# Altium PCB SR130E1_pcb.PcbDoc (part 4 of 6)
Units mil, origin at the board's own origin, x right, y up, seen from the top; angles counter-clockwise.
Board outline 5700 x 4800 mil, 6 copper layers (Top Layer, Signal Layer 1, Signal Layer 2, Signal Layer 3, Signal Layer 4, Bottom Layer), stack 61.4 mil thick; 452 components, 288 nets, 1391 pads, 911 vias.
Unrouted connection lines stored in the file: 523.
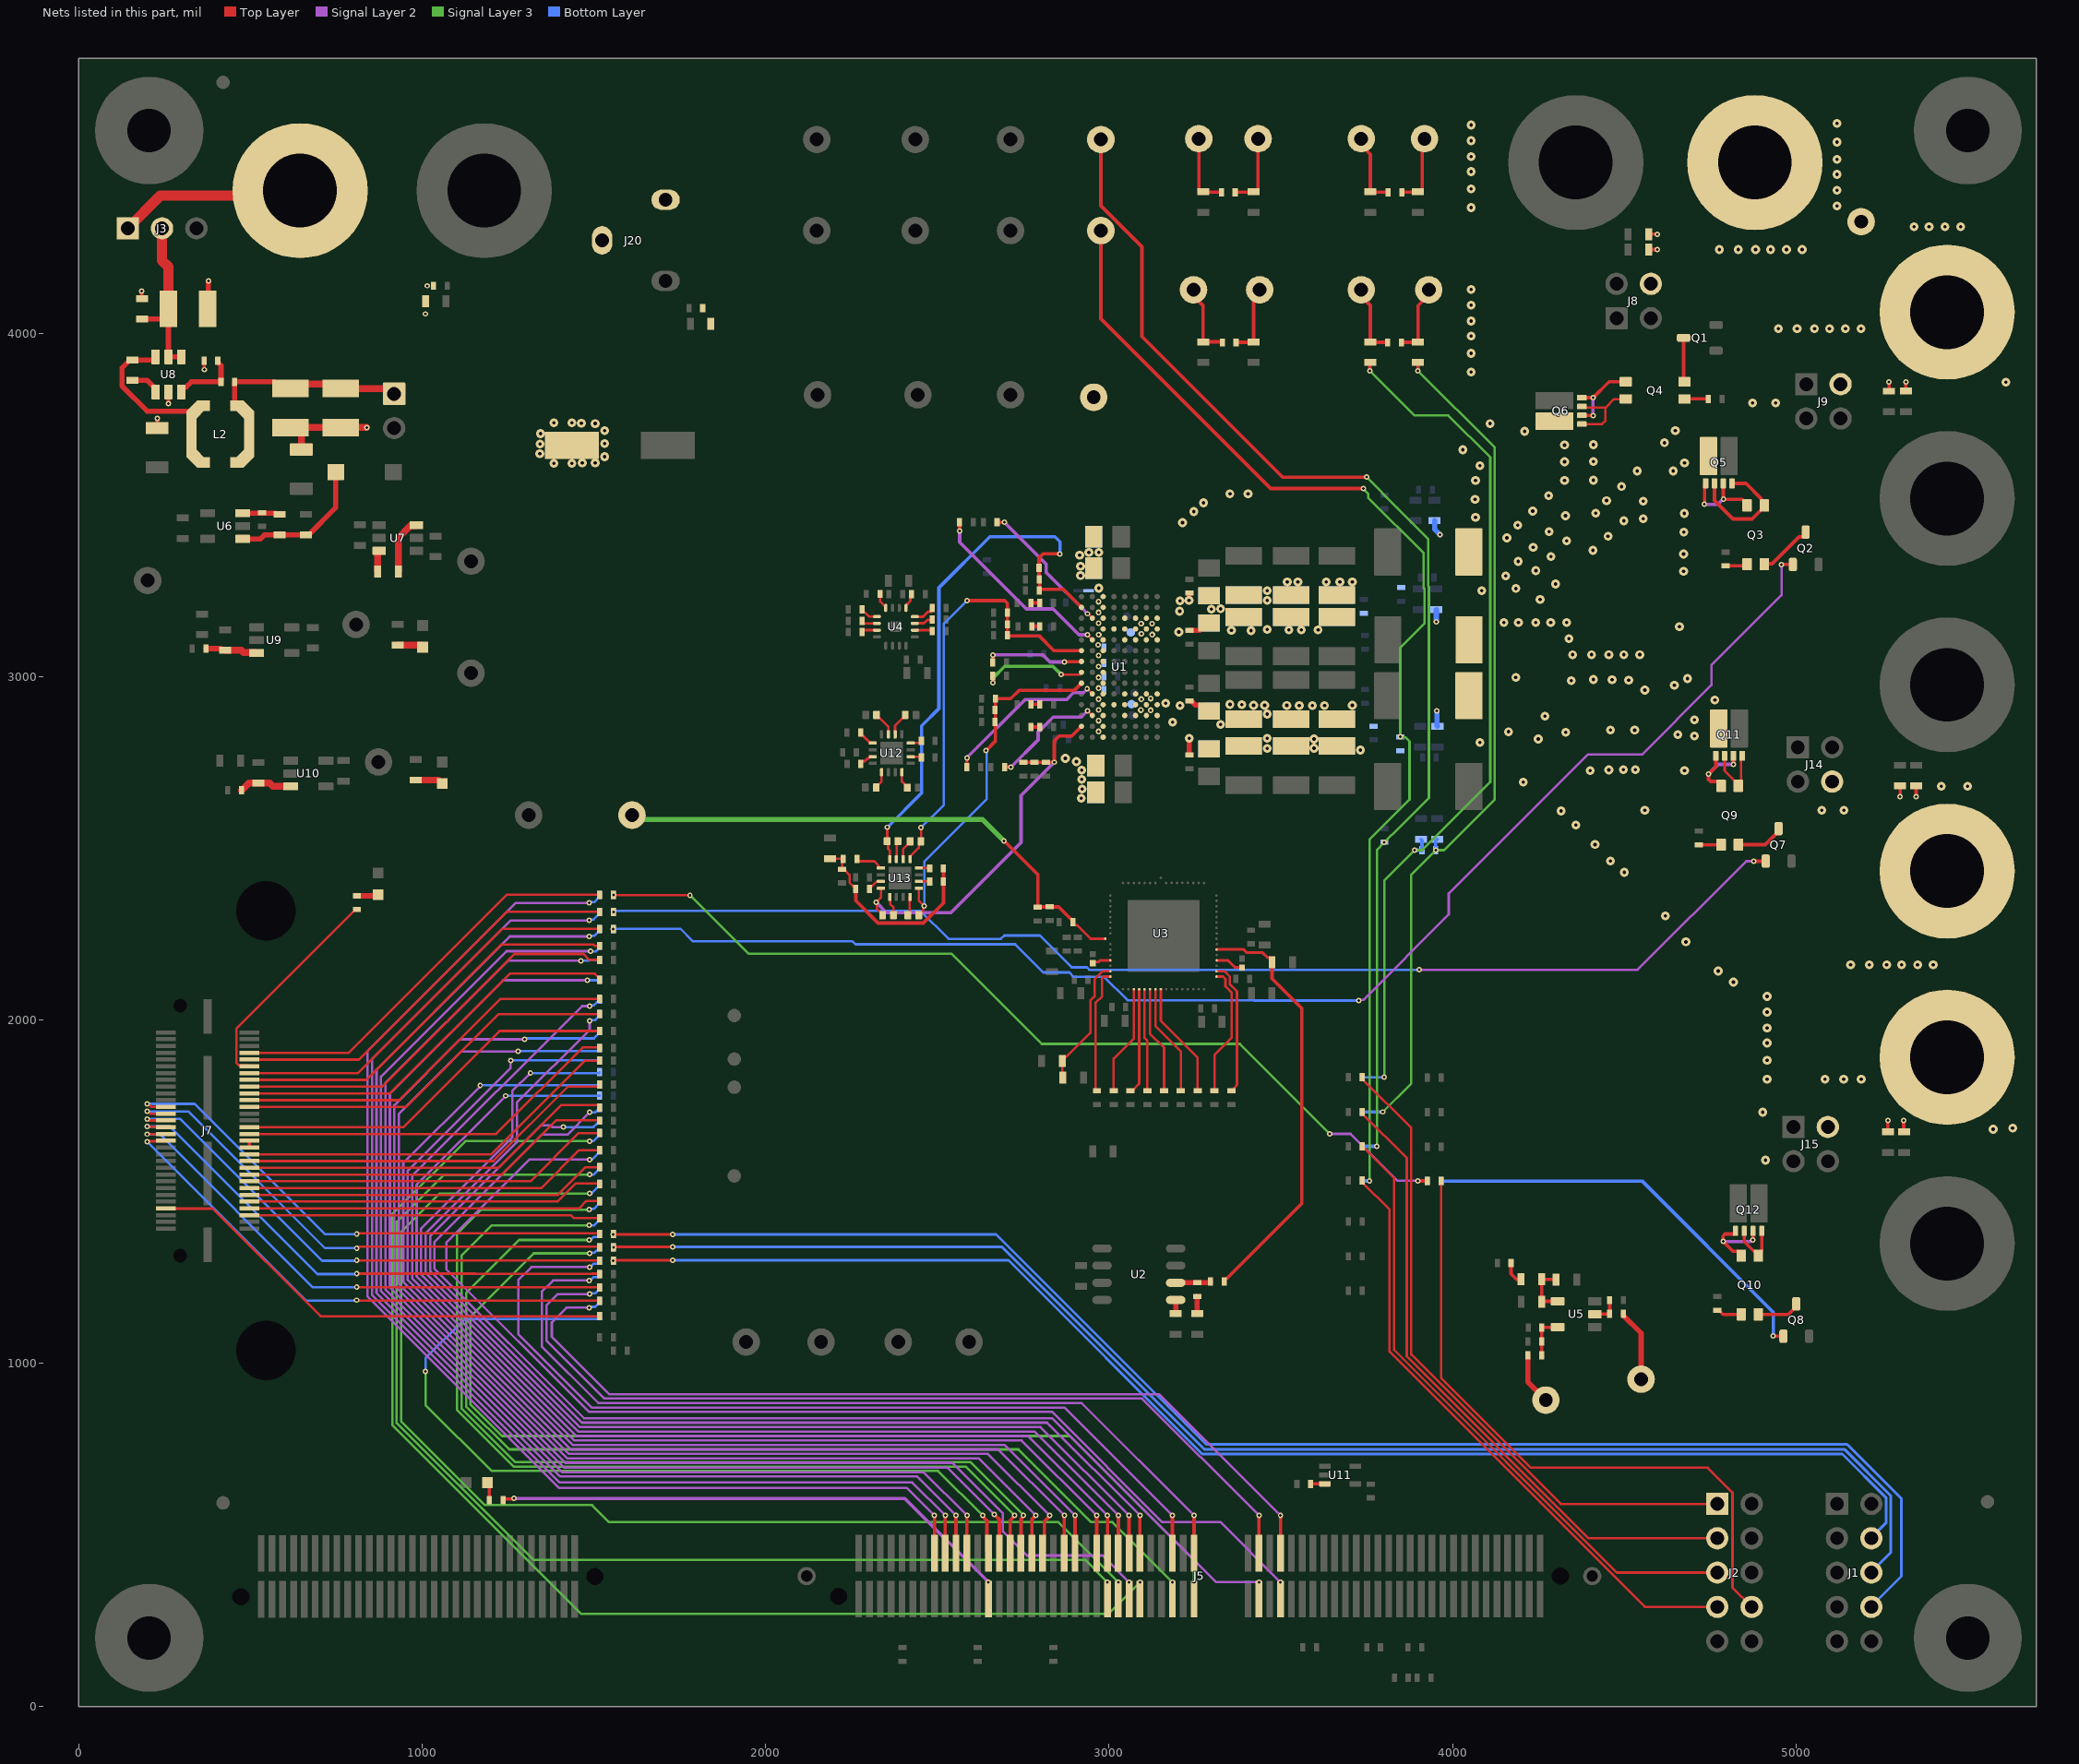
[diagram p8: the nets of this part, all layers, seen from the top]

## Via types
v1: diameter 26, hole 10, Top Layer to Bottom Layer, tented both sides, 435 vias
v2: diameter 16, hole 8, Top Layer to Bottom Layer, tented both sides, 208 vias
v3: diameter 16, hole 8, Top Layer to Bottom Layer, 145 vias
v4: diameter 16, hole 8, Top Layer to Bottom Layer, tented bottom, 46 vias
v5: diameter 19.68, hole 8, Top Layer to Bottom Layer, tented both sides, 35 vias
v6: diameter 17, hole 8, Top Layer to Bottom Layer, 30 vias
v7: diameter 18, hole 8, Top Layer to Bottom Layer, tented both sides, 6 vias
v8: diameter 16, hole 8, Top Layer to Bottom Layer, tented top, 4 vias
v9: diameter 19.68, hole 8, Top Layer to Bottom Layer, 1 vias
v10: diameter 17, hole 8, Top Layer to Bottom Layer, tented both sides, 1 vias

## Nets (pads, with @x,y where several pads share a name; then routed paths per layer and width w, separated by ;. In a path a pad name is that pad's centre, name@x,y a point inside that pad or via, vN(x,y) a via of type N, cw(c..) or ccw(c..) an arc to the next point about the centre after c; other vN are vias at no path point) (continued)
EN_RLY2: Q2.1 R134.1 R166.1 | length 4168.7
  Top Layer w10: v4(4958.09,3326.01) Q2.1@4991.18,3326.01
  Signal Layer 2 w7: v4(3727.26,2056.06) 3729.18,2057.97 3740.14,2057.97 3989.14,2306.97 3989.14,2368.14 4393.77,2772.78 4551.73,2772.78 4754.05,2975.09 4754.05,3032.49 4958.09,3236.53 v4(4958.09,3326.01)
  Bottom Layer w7: R134.1@1557.16,2264.65 1557.64,2265.13 1751.77,2265.13 1787.66,2229.24 2252.6,2229.24 2261.8,2220.04 2726.74,2220.04 2808.73,2138.06 2884.4,2138.06 2897.4,2125.06 2985.84,2125.06 3053.74,2057.15 3421.8,2057.15 3422.9,2056.06 v4(3727.26,2056.06)
  other v3: 1556.67,2264.16
EN_RLY3: Q7.1 R135.1 R167.1 | length 3570.1
  Top Layer w7: R167.1@1557.16,2314.38 R167.1@1559.67,2316.9 ; Q7.1@4911.79,2461.82 Q7.1@4912.23,2462.26
  Top Layer w10: v4(4877.1,2461.82) Q7.1@4911.79,2461.82
  Signal Layer 2 w7: v4(3903.67,2145.63) 3903.81,2145.49 4538.98,2145.49 4855.31,2461.82 v4(4877.1,2461.82)
  Bottom Layer w7: R135.1@1557.16,2314.72 1559.34,2316.9 1810,2316.9 2451.4,2316.9 2532.75,2235.55 2685.3,2235.55 2695.31,2245.56 2798.38,2245.56 2891.03,2152.91 2935.42,2152.91 2942.77,2145.56 3903.6,2145.56 v4(3903.67,2145.63)
  other v3: 1557.44,2314.67
EN_RLY4: Q8.1 R68.1 | length 1224.3
  Top Layer w10: v3(4934.22,1079.67) 4934.89,1079.01 4962.91,1079.01 Q8.1@4963.57,1078.35
  Bottom Layer w10: R68.1@3966.8,1530.55 4552.02,1530.55 4934.22,1148.34 v3(4934.22,1079.67)
EN_RLY4_H: R68.2 R69.2 R136.1 R168.1 | length 2744.3
  Top Layer w7: v3(1557.16,2363.94) 1558.22,2362.87 v3(1780,2362.87)
  Top Layer w10: v2(3899.32,1531.1) 3899.6,1530.83 3926.53,1530.83 R69.2@3926.8,1530.55
  Signal Layer 2 w7: v4(3642.98,1668) 3703.25,1668 3840.14,1531.1 v2(3899.32,1531.1)
  Signal Layer 3 w7: v3(1780,2362.87) 1950.36,2192.51 2541,2192.51 2803.78,1929.73 3381.25,1929.73 v4(3642.98,1668)
  Bottom Layer w7: R136.1@1557.16,2363.65 R136.1@1558.41,2364.91
  Bottom Layer w10: v2(3899.32,1531.1) 3899.6,1530.83 3926.53,1530.83 R68.2@3926.8,1530.55
EN_RLY4_header: J2.8 R69.1 | length 1916.6
  Top Layer w7: R69.1@3966.8,1530.55 3966.8,956.93 4228.33,695.4 4743.31,695.4 4815.51,623.2 4815.51,345.95 J2.8@4871.22,290.24
EPWM_EX_1: J1.4 R119.1 R174.2 | length 4125.6
  Top Layer w8: R174.2@1557.16,1298.37 1558.3,1299.52 v3(1730,1299.52)
  Bottom Layer w8: v3(1730,1299.52) 2707.29,1299.52 3271.4,735.4 5135.17,735.4 5262.15,608.42 5262.15,534.61 J1.4@5219.67,492.13
  other v3: 1556.76,1297.97
EPWM_EX_2: J1.6 R140.2 R175.2 | length 4264.7
  Top Layer w8: R175.2@1557.16,1337.17 1558.13,1338.15 v3(1730,1338.15)
  Bottom Layer w8: v3(1730,1338.15) 2688.46,1338.15 3277.2,749.4 5140.97,749.4 5276.15,614.22 5276.15,448.61 J1.6@5219.67,392.13
  other v3: 1557.43,1337.17
EPWM_EX_3: J1.8 R141.2 R176.2 | length 4419
  Top Layer w8: R176.2@1557.16,1375.98 1558.1,1375.03 v3(1730,1375.03)
  Bottom Layer w8: v3(1730,1375.03) 2671.38,1375.03 3282.5,763.91 5149.16,763.91 5307.15,605.91 5307.15,379.61 J1.8@5219.67,292.13
  other v3: 1556.18,1375.01
FB1: D9.1 R26.1 R27.2 R28.1 U1.A13 U13.16 | length 1619.9
  Top Layer w7: v2(2354.77,2560.63) 2354.36,2560.23 2354.36,2520.66 D9.1@2353.96,2520.25 2356.97,2517.24 2356.97,2497.94 2361.38,2493.53 U13.16@2361.38,2467.89
  Top Layer w10: v2(2857.31,3356.88) 2807.59,3356.88 2796.23,3345.53 R26.1@2796.23,3316.25 2796.42,3316.06 2796.42,3284.63 2797.93,3283.12 2797.93,3250.67 2797.87,3250.61 2797.87,3253.74 2867.2,3253.74 U1.A13@2919.84,3201.1
  Bottom Layer w10: v2(2354.77,2560.63) 2454.63,2660.5 2454.63,2856.24 2504.64,2906.25 2504.64,3258.28 2653.37,3407 2842.44,3407 2857.31,3392.14 v2(2857.31,3356.88)
FB2: D12.1 R29.1 R30.2 R34.1 U1.A9 U13.13 | length 1271.2
  Top Layer w7: U13.13@2420.44,2467.89 2421.66,2469.12 2421.66,2476.21 2446.23,2500.78 2446.23,2513.65 D12.1@2452.58,2520 ; D12.1@2452.54,2520.03 v2@2452.54,2559.34
  Top Layer w10: v2(2586.16,3221) 2696.17,3221 2704.19,3212.98 2704.19,3183.67 2704.31,3183.55 R34.1@2704.31,3151.74 2704.31,3118.44 2796.19,3118.44 2839.52,3075.12 U1.A9@2919.84,3075.12
  Bottom Layer w7: v2(2452.51,2559.37) 2519.34,2626.19 2519.34,3154.18 v2(2586.16,3221)
FB3: D11.1 R38.2 R39.1 R52.1 U1.A6 U13.9 | length 1053.4
  Top Layer w7: D11.1@2445.95,2304.57 2445.95,2306.54 2460.18,2320.77 2460.18,2329.43 v2(2461.9,2331.15) 2445.99,2347.06 2445.99,2382.02 2446.03,2382.06 U13.9@2446.03,2383.25
  Top Layer w10: v2(2641.82,2783.86) 2668.97,2811.01 2668.97,2870.49 2668.97,2902.01 R38.2@2668.97,2935.46 2713.82,2935.46 2737.62,2959.26 2898.47,2959.26 U1.A6@2919.84,2980.63
  Bottom Layer w7: v2(2461.9,2331.15) 2461.9,2461.03 2644.03,2643.16 2644.03,2779.21 2641.82,2781.42 v2(2641.82,2783.86)
FB4: D10.1 R32.1 R33.2 R36.1 U1.A2 U13.4 | length 1134.5
  Top Layer w7: U13.4@2335.79,2383.25 2335.79,2356.24 v2(2322.03,2342.48) 2323.55,2340.96 2323.55,2323.98 2340.99,2306.54 D10.1@2340.99,2304.57
  Top Layer w10: R36.1@2750.26,2750.14 R36.1@2750.89,2750.14 R33.2@2783.14,2750.14 R32.1@2815.92,2750.14 2819.04,2750.14 2819.1,2750.08 2840.68,2750.08 v2(2840.74,2750.02) ; v2@2840.62,2750.14 2840.74,2750.26 2840.74,2812.12 2855.43,2826.81 2892,2826.81 U1.A2@2919.84,2854.64
  Signal Layer 2 w10: v2(2322.03,2342.48) 2352.36,2312.15 2539.95,2312.15 2743.77,2515.97 2743.77,2653.04 v2(2840.74,2750.02)
HVSS: C84.2 R85.1 R89.1 TP26.1 U3.25 | length 1591.5
  Top Layer w7: R85.1@2892.57,2285.57 2892.57,2281.23 2897.54,2276.26 2906.41,2276.26 2946.48,2236.18 U3.25@2989.41,2236.18
  Top Layer w10: v4(2693.95,2521.39) 2792.66,2422.68 2792.66,2328.18 2793.16,2328.68 2826.33,2328.68 C84.2@2826.7,2329.06 ; C84.2@2824.61,2331.14 C84.2@2826.7,2329.06 ; R85.1@2892.57,2285.57 2892.57,2290.07 2853.58,2329.06 C84.2@2826.7,2329.06
  Signal Layer 3 w15: TP26.1@1611.19,2596.17 1623.57,2583.79 2631.55,2583.79 v4(2693.95,2521.39)
ISEN4+_header: J2.1 R43.1 | length 1937.9
  Top Layer w7: R43.1@3737.27,1832.72 3737.27,1828.22 3879.91,1685.57 3879.91,1025.44 4315.11,590.24 J2.1@4771.22,590.24
ISEN4+_powerSch: C67.2 R18.2 R42.1 R56.1 | length 2545.3
  Top Layer w7: v2@3759.2,3889.9 v2(3759.45,3889.9)
  Top Layer w10: v2@3759.2,3889.9 3759.45,3890.15 3759.45,3912.84 R18.2@3761.04,3914.42
  Signal Layer 3 w7: v2(3759.45,3889.9) 3889.23,3760.12 3988.46,3760.12 4110,3638.58 4110,2692.37 3911.64,2494.01 3889.66,2494.01 3801.73,2406.07 v2(3801.73,1832.72)
  Bottom Layer w7: R42.1@3737.27,1832.72 v2(3801.73,1832.72)
  Bottom Layer w10: v2(3890.07,2494.01) 3908.73,2494.01 3908.83,2494.11 C67.2@3911.23,2494.11 3911.23,2522.87 R56.1@3908.18,2525.92
ISEN4-_header: J2.3 R45.1 | length 1889.1
  Top Layer w7: R45.1@3737.27,1731.68 3737.27,1727.18 3866.91,1597.54 3866.91,1020.05 4396.73,490.24 J2.3@4771.22,490.24
ISEN4-_powerSch: C67.1 R19.2 R44.1 R59.1 | length 2518.2
  Top Layer w10: v2(3899.6,3889.9) R19.2@3899.6,3914.42
  Signal Layer 3 w7: v2(3797.52,1731.68) 3879.91,1814.07 3879.91,2422.59 v2(3951.33,2494.01) 3975.32,2494.01 4123,2641.68 4123,3666.5 v2(3899.6,3889.9)
  Bottom Layer w10: R44.1@3737.27,1731.68 v2(3797.52,1731.68) ; v2(3951.33,2494.01) C67.1@3951.23,2494.11 3951.23,2521.41 R59.1@3955.74,2525.92
LED_BLINK_C2K: J5.96 R148.2 | length 1565.7
  Top Layer w10: R148.2@1235.69,601.61 1235.69,601.71 1238.19,604.21 1265.55,604.21 v3(1267.46,606.12) ; J5.96@2649.09,313.07 v3(2649.09,362.57)
  Signal Layer 2 w10: v3(1267.46,606.12) 2405.54,606.12 v3(2649.09,362.57)
LED_BLINK_PHI: J7.50 R169.2 | length 636.8
  Top Layer w7: J7.50@497,1864.56 494.5,1867.06 466.27,1867.06 459,1874.33 459,1974.59 805.5,2321.09 R169.2@810,2321.09
LENS4-_powerSch: R48.1 R73.2 TP21.1 | length 3435.5
  Top Layer w10: TP21.1@2976.27,4298.34 2976.27,4041.56 3470.74,3547.08 v2(3741.19,3547.08)
  Signal Layer 3 w7: v2(3741.19,3547.08) 3741.19,3545.46 3754.62,3532.02 3754.62,3520.92 3916.31,3359.23 3916.31,3257.9 3918.55,3255.67 3918.55,3154.33 3848.13,3083.91 v2(3848.13,2824.67) 3849.85,2822.95 3862.98,2822.95 3874.95,2810.98 3874.95,2641.36 3758.41,2524.83 3758.41,1530.9 v2(3758.77,1530.55)
  Bottom Layer w10: R48.1@3737.27,1531.68 3737.83,1531.12 3758.2,1531.12 v2(3758.77,1530.55) ; v2(3848.13,2824.67) 3848.13,2824.33 R73.2@3848.33,2824.12
LSEN4+_header: J2.5 R47.1 | length 1843.9
  Top Layer w7: R47.1@3737.27,1631.68 3737.27,1627.18 3741.27,1623.18 3745.77,1623.18 3830.02,1538.93 3830.02,1038.56 4478.34,390.24 J2.5@4771.22,390.24
LSEN4+_powerSch: R23.2 R46.1 TP17.1 | length 3577.3
  Top Layer w10: TP17.1@2976.27,4563.77 2976.27,4370.46 3095.77,4250.96 3095.77,3990.14 3505.54,3580.37 v2(3749.84,3580.37)
  Signal Layer 3 w7: v2(3749.84,3580.37) 3839.09,3491.12 3839.09,3490.88 3929.31,3400.65 3929.31,3263.29 3931.55,3261.05 3931.55,2646.15 3847.19,2561.8 v2(3801.73,2516.33) 3780.02,2494.63 v2(3780.02,1631.68)
  Bottom Layer w10: R46.1@3737.27,1631.68 v2(3780.02,1631.68) ; v2(3801.73,2516.33) 3801.73,2517.05 R23.2@3801.85,2517.18
LSEN4-_header: J2.7 R49.1 | length 1793.5
  Top Layer w7: R49.1@3737.27,1531.68 3737.27,1527.18 3817.02,1447.43 3817.02,1033.17 4559.96,290.24 J2.7@4771.22,290.24
MSEL1: R1.2 U1.A8 | length 289.2
  Top Layer w10: R1.2@2661.65,3040.57 2661.79,3040.71 2661.79,3062.53 v2(2661.93,3062.68) ; v2(2870.59,3042.26) 2871.27,3042.94 2919.16,3042.94 U1.A8@2919.84,3043.62
  Signal Layer 2 w10: v2(2661.93,3062.68) 2807.55,3062.68 2827.96,3042.26 v2(2870.59,3042.26)
MSEL2: R7.2 U1.A7 | length 318.8
  Top Layer w7: v2@2859.71,3005.53 v2(2860.42,3005.53) 2914.7,3005.53 2919.84,3010.67 U1.A7@2919.84,3012.12
  Top Layer w10: v2(2661.99,2982.3) 2662.16,2982.48 2662.16,3001.82 R7.2@2662.34,3002
  Signal Layer 3 w10: v2(2661.99,2982.3) 2663.14,2983.45 2663.14,2996.31 2696.02,3029.2 2836.9,3029.2 2860.42,3005.67 v2(2860.42,3005.53)
NetC2_1: C2.1 R3.1 | length 26
  Top Layer w10: C2.1@2772.42,3214 R3.1@2798.42,3214
NetC3_1: C3.1 R4.1 | length 26
  Top Layer w10: C3.1@2772.42,2919 R4.1@2798.42,2919
NetC5_1: C5.1 R5.1 TP1.1 | length 218.5
  Top Layer w10: TP1.1@3261.15,4566.08 3261.65,4565.58 3261.65,4416.25 3266.65,4411.25 R5.1@3274.15,4411.25 3275.15,4410.25 3326.24,4410.25 C5.1@3327.24,4409.25
NetC5_2: C5.2 R6.1 TP2.1 | length 219.3
  Top Layer w10: C5.2@3367.24,4409.25 3368.24,4410.25 3420.1,4410.25 R6.1@3421.1,4411.25 3428.6,4411.25 3433.6,4416.25 3433.6,4565.56 TP2.1@3434.13,4566.08
NetC11_1: C11.1 R9.1 | length 26
  Top Layer w10: C11.1@2772.42,3146 R9.1@2798.42,3146
NetC12_1: C12.1 R10.1 | length 26
  Top Layer w10: C12.1@2772.42,2853 R10.1@2798.42,2853
NetC25_1: C25.1 R11.1 TP5.1 | length 219
  Top Layer w10: TP5.1@3246.05,4126.08 3246.05,4107.14 3274.15,4079.05 R11.1@3274.15,3974.42 C25.1@3329.83,3974.42
NetC25_2: C25.2 R12.1 TP6.1 | length 211.1
  Top Layer w10: C25.2@3369.83,3972.42 3370.83,3973.42 3420.1,3973.42 R12.1@3421.1,3974.42 3421.1,4108.44 TP6.1@3438.75,4126.08
NetC30_1: C30.1 R14.1 TP8.1 | length 218.1
  Top Layer w10: TP8.1@3734.37,4566.08 3734.37,4547.14 3761.04,4520.48 R14.1@3761.04,4411.39 3762.04,4410.39 3811.52,4410.39 C30.1@3812.52,4409.39
NetC30_2: C30.2 R15.1 TP9.1 | length 214.9
  Top Layer w10: C30.2@3852.52,4409.39 3853.52,4410.39 3898.6,4410.39 R15.1@3899.6,4411.39 3907.1,4411.39 3912.1,4416.39 3912.1,4559.42 TP9.1@3918.76,4566.08
NetC55_1: C55.1 R18.1 TP12.1 | length 213.9
  Top Layer w10: TP12.1@3734.37,4126.08 3734.37,4107.14 3761.04,4080.48 R18.1@3761.04,3974.42 3762.04,3973.42 3810.43,3973.42 C55.1@3811.43,3972.42
NetC55_2: C55.2 R19.1 TP13.1 | length 213.7
  Top Layer w10: C55.2@3851.43,3972.42 3852.43,3973.42 3898.6,3973.42 R19.1@3899.6,3974.42 3899.6,4079.69 3930.99,4111.07 TP13.1@3930.99,4126.08
NetC69_1: C69.1 U2.5 | length 39.5
  Top Layer w15: C69.1@3194.25,1144.64 U2.5@3194.25,1184.14
NetC72_1: C72.1 R75.1 | length 55.5
  Top Layer w15: R75.1@3256.6,1194.14 3256.6,1148.93 3252.44,1144.77 C72.1@3256.85,1144.77
NetC85_1: C85.1 U3.52 | length 82.1
  Top Layer w8: U3.52@3313.64,2173.19 3346.6,2173.19 3367.47,2152.32 C85.1@3387.09,2152.32
NetC87_1: C87.1 U3.29 | length 51.7
  Top Layer w8: C87.1@2954.97,2167.13 2956.15,2168.31 2968.74,2168.31 2973.62,2173.19 U3.29@3004.17,2173.19
NetC92_1: C92.1 L1.2 R107.1 U6.1 | length 412.7
  Top Layer w15: U6.1@477.5,3400.62 529.14,3400.62 540.66,3412.15 R107.1@585.64,3412.15 C92.1@661.55,3412.15 669.05,3412.15 748.72,3491.82 L1.2@748.72,3595.53
NetC93_2: C93.2 R107.2 U6.3 | length 109.5
  Top Layer w15: U6.3@477.5,3475.43 574.87,3475.43 578.14,3472.15 R107.2@585.64,3472.15
NetC96_1: C96.1 U7.3 | length 165.8
  Top Layer w20: C96.1@930.61,3305.83 930.61,3403.66 965.86,3438.92 981.41,3438.92 U7.3@983.22,3440.73
NetC96_2: C96.2 U7.6 | length 63.4
  Top Layer w20: C96.2@870.61,3305.83 870.61,3364.11 872.42,3365.92 U7.6@874.95,3365.92
NetC97_1: C97.1 C99.1 J3.2 U8.4 U8.5 | length 496.8
  Top Layer w15: C99.1@184.06,4040.58 260.69,4040.58 C97.1@261.28,4040 ; C97.1@261.28,4070.58 C97.1@261.28,4040 ; U8.4@298.68,3930.68 U8.5@261.28,3930.68 C97.1@261.28,4040
  Top Layer w30: J3.2@242.74,4304.95 242.74,4211.38 261.28,4192.85 C97.1@261.28,4070.58
NetC100_2: C100.2 R108.2 U9.3 | length 153.1
  Top Layer w15: C100.2@370.42,3081.23 413.45,3081.23 418.82,3075.86 R108.2@426.32,3075.86
  Top Layer w20: R108.2@426.32,3075.86 473.82,3075.86 479.41,3070.27 516.38,3070.27 U9.3@518.19,3068.46
NetC102_1: C102.1 L2.1 U8.6 | length 613.1
  Top Layer w15: U8.6@223.87,3930.68 223.87,3926.18 219.56,3921.87 C102.1@156.79,3921.87 149.29,3921.87 125.79,3898.37 125.79,3846.27 199.34,3772.73 L2.1@339.44,3772.73 ; L2.1@364.06,3623.09 361.11,3623.09 337.86,3646.33 335.89,3646.33 328.63,3653.6 L2.1@328.63,3705.76 328.63,3754.01 335.89,3761.27 335.89,3769.18 L2.1@339.44,3772.73 ; L2.1@364.06,3788.44 351.29,3775.67 L2.1@342.39,3775.67 L2.1@339.44,3772.73
NetC102_2: C102.2 U8.1 | length 86.7
  Top Layer w15: C102.2@156.79,3861.87 200.17,3861.87 223.87,3838.17 U8.1@223.87,3828.32
NetC104_1: C104.1 C105.1 J4.1 L2.2 R109.2 | length 761.5
  Top Layer w15: L2.2@460.52,3623.09 468.77,3631.33 473.69,3631.33 495.95,3653.6 L2.2@495.95,3705.76 495.95,3757.93 488.69,3765.19 486.72,3765.19 463.47,3788.44 L2.2@460.52,3788.44 454.31,3794.65 R109.2@454.31,3857.85 571,3857.85 589.44,3839.41 C104.1@617,3839.41
  Top Layer w20: C104.1@617,3839.41 629.53,3851.94 749.66,3851.94 C105.1@762.9,3838.71 903.12,3838.71 J4.1@918.65,3823.18
NetC107_2: C107.2 R114.2 U10.3 | length 156.2
  Top Layer w20: C107.2@474.09,2668.25 474.59,2668.25 495.71,2689.37 R114.2@522.97,2689.37 556.68,2689.37 566.04,2680 U10.3@617.7,2680
NetD1_2: D1.2 R111.1 | length 74.9
  Top Layer w20: R111.1@929.38,3091.73 995.03,3091.73 D1.2@1001.57,3085.19
NetD2_2: D2.2 R115.1 | length 81.4
  Top Layer w20: R115.1@981.48,2698.23 1048.25,2698.23 D2.2@1058.6,2687.87
NetD3_2: D3.2 R148.1 | length 53
  Top Layer w10: D3.2@1190.45,652.49 1195.69,647.26 R148.1@1195.69,601.61
NetD4_2: D4.2 R169.1 | length 63.7
  Top Layer w15: R169.1@810,2361.09 868.66,2361.09 D4.2@872.19,2364.62
NetD5_1: D5.1 U12.15 | length 71.8
  Top Layer w7: D5.1@2323.08,2887.97 2323.08,2886 2329.42,2879.66 2331.39,2879.66 2357.46,2853.59 U12.15@2357.46,2831.59
NetD6_1: D6.1 U12.5 | length 51.4
  Top Layer w7: D6.1@2322.03,2676.48 2322.03,2678.44 2337.78,2694.19 U12.5@2337.78,2721.36
NetD7_1: D7.1 U12.8 | length 52
  Top Layer w7: U12.8@2396.83,2721.36 2396.83,2693.98 2412.86,2677.96 D7.1@2412.86,2675.99
NetD8_1: D8.1 U12.14 | length 68.6
  Top Layer w7: U12.14@2377.15,2831.59 2377.15,2856.47 2406.67,2886 D8.1@2406.67,2887.97
NetD9_2: D9.2 U13.15 | length 54.2
  Top Layer w7: U13.15@2381.07,2467.89 2382.29,2469.12 2382.29,2517.09 D9.2@2385.46,2520.25
NetD10_2: D10.2 U13.5 | length 57.7
  Top Layer w7: U13.5@2361.38,2357.66 2362.61,2356.43 2362.61,2336.76 2372.49,2326.88 D10.2@2372.49,2304.57
NetD11_2: D11.2 U13.8 | length 55.6
  Top Layer w7: D11.2@2414.45,2304.57 2419.21,2309.33 2419.21,2356.43 U13.8@2420.44,2357.66
NetD12_2: D12.2 U13.14 | length 60.5
  Top Layer w7: U13.14@2400.75,2467.89 2400.75,2497.7 2421.08,2518.03 D12.2@2421.08,2520
NetJ5_49: J5.49 R116.2 | length 2657.4
  Top Layer w10: J5.49@3499.49,446.93 v3(3499.49,556.62)
  Signal Layer 2 w7: v3(1486.8,1161.67) 1420.18,1161.67 1377.51,1119 1377.51,1077.32 1544.84,910 3146.1,910 v3(3499.49,556.62)
  Bottom Layer w7: v3(1486.8,1161.67) 1489.29,1164.16 1503.85,1164.16 1517.16,1177.46 R116.2@1517.16,1181.96
NetJ5_50: J5.50 R138.1 | length 3494
  Top Layer w10: J5.50@3499.49,313.07 v3(3499.49,362.57)
  Signal Layer 2 w7: v3(1487.74,1592.86) 1312.36,1592.86 1070.45,1350.95 1070.45,1273.58 1486.04,858 2834.62,858 3155.5,537.12 3324.93,537.12 v3(3499.49,362.57)
  Bottom Layer w7: v3(1487.74,1592.86) 1494.7,1592.86 1517.16,1615.32 R138.1@1517.16,1619.82
NetJ5_53: J5.53 R117.2 | length 2677.7
  Top Layer w10: J5.53@3436.49,446.93 v3(3436.49,556.62)
  Signal Layer 2 w7: v3(1487.37,1201.46) 1394.51,1201.46 1361.72,1168.68 1361.72,1066.18 1530.91,897 3096.11,897 v3(3436.49,556.62)
  Bottom Layer w7: v3(1487.37,1201.46) 1489.66,1203.75 1504.64,1203.75 1517.16,1216.26 R117.2@1517.16,1220.76
NetJ5_54: J5.54 R139.1 | length 3551.4
  Top Layer w10: J5.54@3436.49,313.07 v3(3436.49,362.57)
  Signal Layer 2 w7: v3(1487.74,1730.69) 1422.71,1665.66 1348.72,1665.66 1036.14,1353.07 1036.14,1274.84 1470.98,840 2834.23,840 3311.67,362.57 v3(3436.49,362.57)
  Bottom Layer w7: v3(1487.74,1730.69) 1504.19,1730.69 1508.66,1735.15 1513.16,1735.15 1517.16,1739.15 R139.1@1517.16,1743.65
NetJ5_57: J5.57 R118.2 | length 2564.5
  Top Layer w10: J5.57@3247.52,446.93 v3(3247.52,556.62)
  Signal Layer 2 w7: v3(1486.42,1241.02) 1381.07,1241.02 1348.72,1208.67 1348.72,1048.58 1513.3,884 2920.14,884 v3(3247.52,556.62)
  Bottom Layer w7: v3(1486.42,1241.02) 1489.74,1241.02 1499.79,1251.07 1513.16,1251.07 1517.16,1255.07 R118.2@1517.16,1259.57
NetJ5_58: J5.58 R140.1 | length 3126.2
  Top Layer w10: J5.58@3247.52,313.07 v3(3247.52,362.57)
  Signal Layer 3 w7: v3(1487.37,1319.92) 1324.96,1319.92 1140.95,1135.91 1140.95,879.9 1232.85,788 2886.23,788 3247.52,426.72 v3(3247.52,362.57)
  Bottom Layer w7: v3(1487.37,1319.92) 1489.86,1322.41 1502.2,1322.41 1508.66,1328.87 1513.16,1328.87 1517.16,1332.87 R140.1@1517.16,1337.37
NetJ5_61: J5.61 R119.2 | length 2653.6
  Top Layer w10: J5.61@3184.52,446.93 v3(3184.52,556.62)
  Signal Layer 2 w7: v3(1487.22,1280.02) 1317.96,1280.02 1280,1242.06 1280,1084.46 1493.46,871 2870.14,871 v3(3184.52,556.62)
  Bottom Layer w7: v3(1487.22,1280.02) 1490.54,1280.02 1500.4,1289.87 1513.16,1289.87 1517.16,1293.87 R119.2@1517.16,1298.37
NetJ5_62: J5.62 R141.1 | length 3111
  Top Layer w10: J5.62@3184.52,313.07 v3(3184.52,362.57)
  Signal Layer 3 w7: v3(1486.97,1358.92) 1282.33,1358.92 1127.95,1204.54 1127.95,874.51 1253.47,749 2736.26,749 2948.14,537.12 3009.97,537.12 v3(3184.52,362.57)
  Bottom Layer w7: v3(1486.97,1358.92) 1490.48,1358.92 1499.04,1367.48 1513.16,1367.48 1517.16,1371.48 R141.1@1517.16,1375.98
NetJ5_67: J5.67 R120.2 | length 3212
  Top Layer w10: J5.67@3090.04,446.93 v3(3090.04,556.62)
  Signal Layer 2 w7: v3(1411.33,1687.69) 1379.05,1687.69 1374.42,1692.32 1345.65,1692.32 1023.14,1369.8 1023.14,1269.46 1465.6,827 2819.66,827 v3(3090.04,556.62)
  Bottom Layer w7: v3(1411.33,1687.69) 1498.75,1687.69 1508.66,1697.6 1513.16,1697.6 1517.16,1701.6 R120.2@1517.16,1706.1
NetJ5_68: J5.68 R142.1 | length 3811.3
  Top Layer w10: J5.68@3090.04,313.07 v3(3090.04,362.57)
  Signal Layer 3 w7: v3(1487.74,1646.96) 1126.12,1646.96 912.97,1433.81 912.97,820.16 1463.37,269.76 2997.23,269.76 v3(3090.04,362.57)
  Bottom Layer w7: v3(1487.74,1646.96) 1498.46,1646.96 1517.16,1665.66 R142.1@1517.16,1670.16
NetJ5_69: J5.69 R121.2 | length 3422.4
  Top Layer w10: v3(3058.25,556.33) 3058.39,556.18 3058.39,447.08 J5.69@3058.54,446.93
  Signal Layer 2 w7: v3(1487.74,1996.9) 1487.74,1970.74 1275.68,1758.67 1275.68,1643.36 1010.14,1377.82 1010.14,1264.07 1460.21,814 2800.57,814 v3(3058.25,556.33) v3@3058.25,556.91
  Bottom Layer w7: v3(1487.74,1996.9) 1490.23,1999.39 1504,1999.39 1517.16,2012.55 R121.2@1517.16,2017.05
NetJ5_70: J5.70 R143.1 | length 3900.5
  Top Layer w10: J5.70@3058.54,313.07 v3(3058.54,362.57)
  Signal Layer 2 w7: v3(1481.19,2115.19) 1236.06,2115.19 906.14,1785.27 906.14,1220.99 1417.13,710 2543.12,710 2691.07,562.05 2691.07,510 2761.07,440 2981.11,440 v3(3058.54,362.57)
  Bottom Layer w7: v3(1481.19,2115.19) 1515.69,2115.19 R143.1@1517.16,2116.65
NetJ5_71: J5.71 R122.2 | length 3351.4
  Top Layer w10: J5.71@3027.04,446.93 v3(3027.04,556.62)
  Signal Layer 2 w7: v3(1315.19,1844.86) 1262.68,1792.35 1262.68,1657.51 997.14,1391.97 997.14,1258.69 1454.83,801 2782.66,801 v3(3027.04,556.62)
  Bottom Layer w7: v3(1315.19,1844.86) 1514.56,1844.86 R122.2@1517.16,1847.46
NetJ5_72: J5.72 R144.1 | length 3521.6
  Top Layer w10: J5.72@3027.04,313.07 v3(3027.04,362.57)
  Signal Layer 3 w7: v3(1487.74,1494.42) 1051.58,1494.42 938.97,1381.81 938.97,830.93 1183.29,586.62 1494.36,586.62 1543.86,537.12 2852.49,537.12 v3(3027.04,362.57)
  Bottom Layer w7: v3(1487.74,1494.42) 1493.35,1494.42 1517.16,1518.23 R144.1@1517.16,1522.73
NetJ5_73: J5.73 R123.2 | length 3316.6
  Top Layer w10: J5.73@2995.55,446.93 v3(2995.55,556.62)
  Signal Layer 2 w7: v3(1243.18,1778.69) 984.14,1519.65 984.14,1253.3 1449.44,788 2764.17,788 v3(2995.55,556.62)
  Bottom Layer w7: v3(1243.18,1778.69) 1516.45,1778.69 R123.2@1517.16,1779.39
NetJ5_74: J5.74 R145.1 | length 3556.8
  Top Layer w10: J5.74@2995.55,313.07 v3(2995.55,362.57)
  Signal Layer 3 w7: v3(1487.74,1549.36) 1064.08,1549.36 925.97,1411.26 925.97,825.55 1324.81,426.72 2931.4,426.72 v3(2995.55,362.57)
  Bottom Layer w7: v3(1487.74,1549.36) 1499.45,1549.36 1517.16,1567.07 R145.1@1517.16,1571.57
NetJ5_75: J5.75 R124.2 | length 3447.7
  Top Layer w10: J5.75@2964.05,446.93 v3(2964.05,556.62)
  Signal Layer 2 w7: v3(1487.74,2040) 1466.02,2040 971.14,1545.12 971.14,1247.92 1444.06,775 2745.67,775 v3(2964.05,556.62)
  Bottom Layer w7: v3(1487.74,2040) 1490.23,2042.49 1500.45,2042.49 1508.66,2050.7 1513.16,2050.7 1517.16,2054.7 R124.2@1517.16,2059.2
NetJ5_79: J5.79 R125.2 | length 3359.8
  Top Layer w10: J5.79@2901.06,446.93 v3(2901.06,556.62)
  Signal Layer 2 w7: v3(1257.59,1881.83) 1257.59,1859.78 958.14,1560.33 958.14,1242.53 1438.67,762 2695.68,762 v3(2901.06,556.62)
  Bottom Layer w7: v3(1257.59,1881.83) 1516.83,1881.83 R125.2@1517.16,1882.16
NetJ5_81: J5.81 R126.2 | length 3330.4
  Top Layer w10: J5.81@2869.56,446.93 v3(2869.56,556.62)
  Signal Layer 2 w7: v3(1168.77,1809.44) 1168.77,1806.74 945.14,1583.1 945.14,1237.15 1433.29,749 2677.18,749 v3(2869.56,556.62)
  Bottom Layer w7: v3(1168.77,1809.44) 1514.64,1809.44 R126.2@1517.16,1811.96
NetJ5_85: J5.85 R127.2 | length 3453.5
  Top Layer w10: J5.85@2806.57,446.93 2811.41,451.77 2811.41,538.48 2826.85,553.91 v3(2826.85,556.62)
  Signal Layer 2 w7: v3(1280,1907.89) 1114.49,1907.89 932.14,1725.53 932.14,1231.76 1427.9,736 2647.47,736 v3(2826.85,556.62)
  Bottom Layer w7: v3(1280,1907.89) 1281.26,1909.15 1513.16,1909.15 1517.16,1913.15 R127.2@1517.16,1917.65
NetJ5_87: J5.87 R128.2 | length 3474.6
  Top Layer w10: J5.87@2775.08,446.93 2775.08,545.12 v3(2786.57,556.62)
  Signal Layer 2 w7: v3(1298.46,1943.36) 1110.83,1943.36 919.14,1751.68 919.14,1226.38 1422.52,723 2620.19,723 v3(2786.57,556.62)
  Bottom Layer w7: v3(1298.46,1943.36) 1300.95,1945.85 1500.19,1945.85 1517.16,1962.82 R128.2@1517.16,1967.32
NetJ5_89: J5.89 R129.2 | length 2773.5
  Top Layer w10: J5.89@2743.58,446.93 2743.58,546.42 2751.07,553.91 v3(2751.07,556.62)
  Signal Layer 3 w7: v3(1486.8,1401.39) 1203.01,1401.39 1114.95,1313.33 1114.95,869.13 1272.06,712.02 2597.25,712.02 2751.07,558.2 v3(2751.07,556.62)
  Bottom Layer w7: v3(1486.8,1401.39) 1500.67,1401.39 1517.16,1417.88 R129.2@1517.16,1422.38
NetJ5_91: J5.91 R130.2 | length 2835.8
  Top Layer w10: J5.91@2712.08,446.93 2712.08,542.31 2725.07,555.3 v3(2725.07,556.62)
  Signal Layer 3 w7: v3(1486.68,1447.04) 1171.82,1447.04 1101.95,1377.17 1101.95,863.75 1266.67,699.02 2582.67,699.02 v3(2725.07,556.62)
  Bottom Layer w7: v3(1486.68,1447.04) 1489.17,1449.53 1499.64,1449.53 1517.16,1467.04 R130.2@1517.16,1471.54
NetJ5_93: J5.93 R131.2 | length 3537
  Top Layer w10: v3(2666.51,559.03) 2680.59,544.95 J5.93@2680.59,446.93
  Signal Layer 2 w7: v3(1461.71,2172.18) 1249.64,2172.18 893.14,1815.67 893.14,1215.61 1412.75,696 2529.54,696 v3(2666.51,559.03)
  Bottom Layer w7: v3(1461.71,2172.18) 1461.91,2172.37 1485.71,2172.37 1487.94,2174.6 R131.2@1518.11,2174.6
NetJ5_95: J5.95 R132.2 | length 2568.7
  Top Layer w10: v3(2631.8,556.62) 2631.8,553.91 2644.25,541.47 2644.25,451.77 J5.95@2649.09,446.93
  Signal Layer 3 w7: v3(1010.14,976.17) 1010.14,878.34 1202.46,686.02 2502.4,686.02 v3(2631.8,556.62)
  Bottom Layer w7: v3(1010.14,976.17) 1010.14,1015.17 1123.33,1128.36 1513.16,1128.36 1517.16,1132.36 R132.2@1517.16,1136.86
NetJ5_99: J5.99 R133.2 | length 3508.9
  Top Layer w10: J5.99@2586.1,446.93 v3(2586.1,556.62)
  Signal Layer 2 w7: v3(1490.4,2199.98) 1245.35,2199.98 880.14,1834.77 880.14,1210.23 1407.36,683 2459.72,683 v3(2586.1,556.62)
  Bottom Layer w7: v3(1490.4,2199.98) 1491.24,2199.14 1505.53,2199.14 1517.16,2210.77 R133.2@1517.16,2215.27
NetJ5_101: J5.101 R134.2 | length 3538.1
  Top Layer w10: J5.101@2554.6,446.93 v3(2554.6,556.62)
  Signal Layer 2 w7: v3(1486.8,2242.78) 1254.92,2242.78 867.14,1855 867.14,1204.84 1401.98,670 2441.22,670 v3(2554.6,556.62)
  Bottom Layer w7: v3(1486.8,2242.78) 1489.29,2245.27 1502.28,2245.27 1517.16,2260.15 R134.2@1517.16,2264.65
NetJ5_103: J5.103 R135.2 | length 3574.7
  Top Layer w10: J5.103@2523.11,446.93 v3(2523.11,556.62)
  Signal Layer 2 w7: v3(1486.8,2289.42) 1257.59,2289.42 854.14,1885.97 854.14,1199.46 1401.11,652.49 2427.24,652.49 v3(2523.11,556.62)
  Bottom Layer w7: v3(1486.8,2289.42) 1489.29,2291.91 1498.84,2291.91 1517.16,2310.22 R135.2@1517.16,2314.72
NetJ5_105: J5.105 R136.2 | length 3606.3
  Top Layer w10: J5.105@2491.61,446.93 v3(2491.61,556.62)
  Signal Layer 2 w7: v3(1486.8,2340.32) 1272.22,2340.32 841.14,1909.24 841.14,1194.07 1398.47,636.74 2411.49,636.74 v3(2491.61,556.62)
  Bottom Layer w7: v3(1486.8,2340.32) 1489.29,2342.81 1500.81,2342.81 1517.16,2359.15 R136.2@1517.16,2363.65
NetJ7_6: J7.6 R149.2 | length 1023.8
  Top Layer w7: J7.6@497,1431.16 1433.25,1431.16 1441.76,1422.65 1473.98,1422.65 1477.5,1422.65 1516.89,1422.65 R149.2@1517.16,1422.38
NetJ7_7: J7.7 R170.1 | length 1393.2
  Top Layer w7: J7.7@254,1450.86 254.6,1450.26 390.57,1450.26 703.97,1136.86 R170.1@1517.16,1136.86
NetJ7_8: J7.8 R150.2 | length 1028.9
  Top Layer w7: J7.8@497,1450.86 1456.43,1450.86 1477.5,1471.93 R150.2@1517.16,1471.93
NetJ7_10: J7.10 R151.2 | length 1043.1
  Top Layer w7: J7.10@497,1470.56 1394.06,1470.56 1447.2,1523.7 1514.95,1523.7 R151.2@1517.16,1521.49
NetJ7_12: J7.12 R152.2 | length 1053.6
  Top Layer w7: J7.12@497,1490.26 1395.38,1490.26 1475.76,1570.65 1516.76,1570.65 R152.2@1517.16,1571.04
NetJ7_14: J7.14 R153.2 | length 1066
  Top Layer w7: J7.14@497,1509.96 1346.19,1509.96 1456.83,1620.6 R153.2@1517.16,1620.6
NetJ7_16: J7.16 R154.2 | length 1078.3
  Top Layer w7: J7.16@497,1529.66 1315.19,1529.66 1455.68,1670.16 R154.2@1517.16,1670.16
NetJ7_18: J7.18 R155.2 | length 1086
  Top Layer w7: J7.18@497,1549.36 1232.43,1549.36 1390.25,1707.19 1516.07,1707.19 R155.2@1517.16,1706.1
NetJ7_20: J7.20 R156.2 | length 1095.8
  Top Layer w7: J7.20@497,1569.06 1222.4,1569.06 1405.1,1751.76 R156.2@1517.16,1751.76
NetJ7_22: J7.22 R157.2 | length 1111
  Top Layer w7: J7.22@497,1588.76 1207.46,1588.76 1423.96,1805.26 1514.4,1805.26 R157.2@1517.16,1802.51
NetJ7_24: J7.24 R158.2 | length 1135.9
  Top Layer w7: J7.24@497,1608.46 1201.2,1608.46 1473.12,1880.38 1506.01,1880.38 1509.65,1880.38 R158.2@1517.16,1872.88
NetJ7_26: J7.26 J7.28 | length 19.7
  Top Layer w10: J7.26@497,1628.16 J7.28@497,1647.86
NetJ7_27: J7.27 R171.1 | length 1565.5
  Top Layer w7: v2(200,1645.16) 201.35,1646.51 252.65,1646.51 J7.27@254,1647.86 ; v2(808.86,1183.58) 810.48,1181.96 R171.1@1517.16,1181.96
  Bottom Layer w7: v2(200,1645.16) 663.2,1181.96 807.23,1181.96 v2(808.86,1183.58)
NetJ7_29: J7.29 R172.1 | length 1557.5
  Top Layer w7: v2(200,1667.16) 200.2,1667.36 253.8,1667.36 J7.29@254,1667.56 ; v2(810,1221.91) 810.39,1221.52 1494.89,1221.52 1495.64,1220.76 R172.1@1517.16,1220.76
  Bottom Layer w7: v2(200,1667.16) 200.4,1667.56 235.24,1667.56 682.04,1220.76 808.86,1220.76 v2(810,1221.91)
NetJ7_30: J7.30 R159.2 | length 1125.1
  Top Layer w7: J7.30@497,1667.56 1215.63,1667.56 1467.45,1919.38 1513.16,1919.38 1514.6,1917.93 R159.2@1517.16,1917.93
NetJ7_31: J7.31 R173.1 | length 1551.2
  Top Layer w7: v2(200,1689.16) 200.95,1688.21 253.05,1688.21 J7.31@254,1687.26 ; v2(810,1260.71) 1154.63,1260.71 1154.83,1260.52 1495.3,1260.52 1495.5,1260.71 1513.16,1260.71 1514.3,1259.57 R173.1@1517.16,1259.57
  Bottom Layer w7: v2(200,1689.16) 200.31,1689.46 265.51,1689.46 695.41,1259.57 808.86,1259.57 v2(810,1260.71)
NetJ7_32: J7.32 R160.2 | length 1136.2
  Top Layer w7: J7.32@497,1687.26 945.1,1687.26 1225.33,1967.49 R160.2@1517.16,1967.49
NetJ7_33: J7.33 R174.1 | length 1545.4
  Top Layer w7: v2(199.85,1711.16) 202.28,1711.16 206.48,1706.96 J7.33@254,1706.96 ; v2(810,1299.52) 1516.01,1299.52 R174.1@1517.16,1298.37
  Bottom Layer w7: v2(199.85,1711.16) 200.15,1711.46 295.92,1711.46 709.02,1298.37 808.86,1298.37 v2(810,1299.52)
NetJ7_35: J7.35 R175.1 | length 1541.9
  Top Layer w7: v2(199.85,1733.16) 202.28,1733.16 208.78,1726.66 J7.35@254,1726.66 ; v2(810,1334.92) 812.44,1334.92 816.94,1339.42 1514.91,1339.42 R175.1@1517.16,1337.17
  Bottom Layer w7: v2@199.86,1733.17 319.07,1733.17 717.33,1334.92 v2(810,1334.92)
NetJ7_37: J7.37 R176.1 | length 1533.9
  Top Layer w7: v2(200,1755.16) 202.44,1755.16 206.93,1750.66 207.43,1750.66 211.73,1746.36 J7.37@254,1746.36 ; v2(810,1375.98) 812.44,1375.98 814.88,1378.42 1514.71,1378.42 R176.1@1517.16,1375.98
  Bottom Layer w7: v2(200,1755.16) 337.82,1755.16 717,1375.98 v2(810,1375.98)
NetJ7_38: J7.38 R161.2 | length 1132.3
  Top Layer w7: J7.38@497,1746.36 952.97,1746.36 1223.5,2016.9 1517.01,2016.9 R161.2@1517.16,2017.05
NetJ7_40: J7.40 R162.2 | length 1142.3
  Top Layer w7: J7.40@497,1766.06 933.53,1766.06 1228.39,2060.93 R162.2@1517.16,2060.93
NetJ7_42: J7.42 R163.2 | length 1175
  Top Layer w7: J7.42@497,1785.76 906.63,1785.76 1255.56,2134.69 1503.13,2134.69 1517.16,2120.66 R163.2@1517.16,2116.16
NetJ7_44: J7.44 R164.2 | length 1188.2
  Top Layer w7: J7.44@497,1805.46 882.93,1805.46 1269.14,2191.68 1469.79,2191.68 1486.87,2174.6 R164.2@1518.11,2174.6
NetJ7_46: J7.46 R165.2 | length 1185.2
  Top Layer w7: J7.46@497,1825.16 837.31,1825.16 1231.62,2219.48 1498.47,2219.48 1502.69,2215.27 R165.2@1517.16,2215.27
NetJ7_48: J7.48 R166.2 | length 1194.1
  Top Layer w7: J7.48@497,1844.86 813.03,1844.86 1232.99,2264.82 R166.2@1517.16,2264.82
NetJ7_52: J7.52 R167.2 | length 1198.3
  Top Layer w7: J7.52@497,1884.26 816.16,1884.26 1246.28,2314.38 R167.2@1517.16,2314.38
NetJ7_54: J7.54 R168.2 | length 1210.7
  Top Layer w7: J7.54@497,1903.96 786.34,1903.96 1246.31,2363.94 1470.73,2363.94 R168.2@1517.16,2363.94
NetQ1_3: Q1.3 Q4.2 | length 129.1
  Top Layer w10: Q1.3@4673,3986.2 4673,3860.86 Q4.2@4675.63,3858.24
NetQ2_3: Q2.3 Q3.2 | length 163.8
  Top Layer w10: Q3.2@4907.85,3326.85 4909.37,3328.38 4930.77,3328.38 5008.75,3406.37 5021.84,3406.37 5028.58,3413.11 Q2.3@5028.58,3420.49
NetQ3_1: Q3.1 R180.1 | length 65
  Top Layer w10: R180.1@4794.85,3322.02 4853.02,3322.02 Q3.1@4857.85,3326.85
NetQ3_3: Q3.3 Q5.2 Q5.4 | length 362.6
  Top Layer w10: Q5.2@4762.8,3562.24 4762.8,3512.67 4816.81,3458.65 4872.32,3458.65 4907.85,3494.18 Q3.3@4907.85,3498.11 4899.07,3506.89 4899.07,3518 4854.83,3562.24 Q5.4@4813.98,3562.24
NetQ3_4: Q3.4 Q5.1 Q5.3 | length 249.8
  Top Layer w10: v4(4733.34,3501.03) 4734.49,3502.18 4734.49,3559.52 Q5.1@4737.2,3562.24 ; Q5.3@4788.39,3562.24 4788.79,3561.83 4788.79,3516.38 v4(4789.19,3515.97) 4843.92,3515.97 4857.85,3502.05 Q3.4@4857.85,3498.11
  Signal Layer 2 w10: v4(4733.34,3501.03) 4772.62,3501.03 4787.57,3515.97 v4(4789.19,3515.97)
NetQ4_1: Q4.1 R179.1 | length 69.6
  Top Layer w10: Q4.1@4675.63,3808.24 R179.1@4745.24,3808.24
NetQ4_3: Q4.3 Q6.2 Q6.4 | length 231.5
  Top Layer w10: Q6.2@4376.69,3760.6 4376.93,3760.36 4409.15,3760.36 v4(4409.4,3760.12) ; Q6.4@4376.69,3811.78 v4(4409.4,3811.78) 4455.85,3858.24 Q4.3@4504.37,3858.24
  Signal Layer 2 w10: v4(4409.4,3760.12) v4(4409.4,3811.78)
NetQ4_4: Q4.4 Q6.1 Q6.3 | length 250.3
  Top Layer w7: Q6.1@4376.69,3735.01 4435.43,3735.01 4445.49,3745.08 4445.49,3782.67 ; Q6.3@4376.69,3786.19 4380.21,3782.67 4445.49,3782.67 ; Q4.4@4504.37,3808.24 4503.52,3807.38 4470.2,3807.38 4445.49,3782.67
NetQ7_3: Q7.3 Q9.2 | length 143.8
  Top Layer w10: Q9.2@4829.77,2510 4910.76,2510 4949.63,2548.88 Q7.3@4949.63,2556.75
NetQ8_3: Q8.3 Q10.2 | length 127.5
  Top Layer w10: Q10.2@4890.86,1142.07 4978.08,1142.07 5000.97,1164.96 Q8.3@5000.97,1172.84
NetQ9_1: Q9.1 R181.1 | length 65.6
  Top Layer w10: R181.1@4717.32,2509.51 Q9.1@4782.88,2509.51
NetQ9_3: Q9.3 Q11.2 Q11.4 | length 192.2
  Top Layer w7: Q11.2@4792.45,2768.73 4792.45,2725.1 Q9.3@4832.36,2685.2 ; Q9.3@4832.36,2681.26 Q9.3@4832.36,2685.2 ; Q11.4@4843.63,2768.73 4839.73,2764.83 4839.73,2692.57 Q9.3@4832.36,2685.2
NetQ9_4: Q9.4 Q11.1 Q11.3 | length 233.8
  Top Layer w10: Q11.1@4766.86,2768.73 4766.86,2736.7 v4(4745.55,2715.39) 4745.55,2699.83 4751.41,2693.98 4773.58,2693.98 4782.36,2685.2 Q9.4@4782.36,2681.26 ; v4(4818.04,2743.71) Q11.3@4818.04,2768.73
  Signal Layer 2 w10: v4(4745.55,2715.39) 4773.87,2743.71 v4(4818.04,2743.71)
NetQ10_1: Q10.1 R182.1 | length 75
  Top Layer w10: R182.1@4771.02,1154.56 4775.52,1154.56 4788.01,1142.07 Q10.1@4840.86,1142.07
NetQ10_3: Q10.3 Q12.2 Q12.4 | length 164.2
  Top Layer w10: Q12.2@4849.58,1385.59 4849.58,1354.43 4877.96,1326.05 4882.08,1326.05 Q10.3@4890.86,1317.27 ; Q10.3@4890.86,1313.33 Q10.3@4890.86,1317.27 ; Q12.4@4900.76,1385.59 4900.76,1327.16 Q10.3@4890.86,1317.27
NetQ10_4: Q10.4 Q12.1 Q12.3 | length 249.2
  Top Layer w10: v4(4788.01,1354.43) 4788.01,1370.36 4793.87,1376.22 4821.11,1376.22 4823.99,1379.1 Q12.1@4823.99,1385.59 ; v4@4788.39,1354.04 4816.39,1326.05 4832.08,1326.05 4840.86,1317.27 Q10.4@4840.86,1313.33 ; v4(4874.87,1358.83) 4875.02,1358.98 4875.02,1385.44 Q12.3@4875.17,1385.59
  Signal Layer 2 w10: v4(4788.01,1354.43) 4868.84,1354.43 4873.25,1358.83 v4(4874.87,1358.83)
NetR74_1: R74.1 R75.2 U2.6 | length 105.7
  Top Layer w15: U2.6@3194.25,1234.14 R75.2@3256.6,1234.14 3295.6,1234.14 R74.1@3295.6,1238.46
NetR76_1: R76.1 U3.37 | length 298.9
  Top Layer w7: U3.37@3103.58,2089.11 3103.58,1947.23 3111.49,1939.31 R76.1@3111.49,1793.45
NetR77_1: R77.1 U3.36 | length 308.7
  Top Layer w7: R77.1@3062.61,1793.45 3067.11,1793.45 3087.83,1814.17 U3.36@3087.83,2089.11
NetR78_1: R78.1 U3.38 | length 313.1
  Top Layer w7: U3.38@3119.33,2089.53 3119.33,1959.75 3160.37,1918.71 R78.1@3160.37,1793.45
NetR79_1: R79.1 U3.35 | length 320.2
  Top Layer w7: R79.1@3013.73,1793.45 3013.73,1886.73 3072.08,1945.08 U3.35@3072.08,2089.53
NetR80_1: R80.1 U3.40 | length 340.5
  Top Layer w7: U3.40@3150.82,2089.53 3150.82,1997.13 3258.13,1889.82 R80.1@3258.13,1793.45
NetR81_1: R81.1 U3.39 | length 326.4
  Top Layer w7: U3.39@3135.08,2089.11 3135.08,1982.14 3209.25,1907.96 R81.1@3209.25,1793.45
NetR82_1: R82.1 U3.49 | length 382.2
  Top Layer w7: R82.1@3307.01,1793.45 3307.01,1897.87 3356.63,1947.49 3356.63,2080.13 3352.53,2084.23 3352.23,2084.23 3339.05,2097.41 3339.05,2118.82 3331.93,2125.94 U3.49@3313.22,2125.94
NetR83_1: R83.1 U3.50 | length 395.8
  Top Layer w7: U3.50@3313.22,2141.69 3335.67,2141.69 3352.05,2125.31 3352.05,2102.79 3357.62,2097.23 3357.91,2097.23 3372.7,2082.44 3372.7,1810.26 3363.89,1801.45 3363.89,1796.95 3360.39,1793.45 R83.1@3355.89,1793.45
NetR84_1: R84.1 U3.32 | length 362.4
  Top Layer w7: R84.1@2960.7,1793.45 2960.7,2049.84 2979.68,2068.82 2979.68,2121.84 2983.78,2125.94 U3.32@3004.17,2125.94
NetR86_2: R86.2 R87.1 U3.31 | length 382.5
  Top Layer w7: R86.2@2864.56,1832.21 2864.56,1878.83 R87.1@2863.78,1879.61 2945.7,1961.52 2945.7,2056.06 2957.9,2068.26 2957.9,2118.45 2981.14,2141.69 U3.31@3004.17,2141.69
  Top Layer w10: R86.2@2864.56,1832.21 R86.2@2865.34,1831.43
NetR90_2: R90.2 U4.2 | length 51.1
  Top Layer w8: U4.2@2434.59,3134.77 R90.2@2485.69,3134.77
NetR91_2: R91.2 U4.3 | length 55.7
  Top Layer w8: U4.3@2434.59,3154.45 2460.68,3154.45 2470.88,3164.65 2484.71,3164.65 R91.2@2485.69,3165.64
NetR92_2: R92.2 U4.4 | length 63.5
  Top Layer w8: U4.4@2434.59,3174.14 2458.4,3174.14 2472.88,3188.61 2482.62,3188.61 2486.12,3192.11 R92.2@2486.12,3196.61
NetR93_2: R93.2 U4.5 | length 46.3
  Top Layer w8: U4.5@2409,3199.73 2409,3206.81 2421.55,3219.36 2421.55,3235.86 R93.2@2425.05,3239.36
NetR94_2: R94.2 U4.8 | length 50.1
  Top Layer w7: R94.2@2333.69,3240.42 2333.69,3217.92 2344.32,3207.28 2348.81,3207.28 2349.94,3206.15 U4.8@2349.94,3199.73
NetR95_2: R95.2 U4.9 | length 50.1
  Top Layer w7: R95.2@2280.9,3190.26 2284.79,3186.37 2289.17,3186.37 2301.4,3174.14 U4.9@2324.35,3174.14
NetR96_2: R96.2 U4.10 | length 48.4
  Top Layer w7: R96.2@2280.9,3161.7 2280.9,3158.45 2284.9,3154.45 U4.10@2324.35,3154.45
NetR97_2: R97.2 U4.11 | length 46.7
  Top Layer w7: R97.2@2280.64,3129.43 2280.64,3130.77 2284.64,3134.77 U4.11@2324.35,3134.77
NetR98_2: R98.2 R99.1 | length 66.9
  Top Layer w10: R98.2@4170.54,1291.18 4170.54,1260.02 4186.38,1244.17 R99.1@4199.69,1244.17
NetR99_2: R99.2 R100.2 R101.1 U5.4 | length 153.8
  Top Layer w10: R101.1@4301.54,1243.16 4300.53,1244.17 R99.2@4259.69,1244.17 4259.88,1243.97 4259.88,1179.56 R100.2@4260.08,1179.37 4260.79,1180.08 U5.4@4306.38,1180.08
NetR102_1: R102.1 R103.1 R104.1 U5.5 | length 128.1
  Top Layer w10: R104.1@4259.53,1022.75 4259.99,1023.22 4259.99,1103.54 R102.1@4260.45,1104 4261.09,1104.64 4305.74,1104.64 U5.5@4306.38,1105.28
NetR104_2: R104.2 TP27.1 | length 151.8
  Top Layer w15: R104.2@4219.53,1022.75 4219.53,945.04 TP27.1@4271.89,892.68
NetR105_1: R105.1 R106.1 U5.2 | length 83.7
  Top Layer w10: U5.2@4414.64,1142.68 4415,1143.04 4457.42,1143.04 R105.1@4457.78,1143.4 R106.1@4457.78,1183.62
NetR105_2: R105.2 TP28.1 | length 211.3
  Top Layer w15: R105.2@4497.78,1143.4 4497.78,1138.9 4549.33,1087.34 TP28.1@4549.33,953.44
NetR109_1: R109.1 R110.2 U8.3 | length 198.9
  Top Layer w15: U8.3@298.68,3828.32 298.68,3838.17 302.99,3842.48 312.83,3842.48 328.2,3857.85 R109.1@414.31,3857.85 414.31,3905.63 405.09,3914.84 R110.2@405.09,3919.34
NetR137_2: R137.2 U11.3 | length 41.5
  Top Layer w10: R137.2@3587.26,648.67 U11.3@3628.75,648.67
NetR183_1: R183.1 U12.1 | length 50.5
  Top Layer w8: R183.1@2276.86,2836.21 2276.86,2831.71 2280.36,2828.21 2282.89,2828.21 2304.37,2806.73 2311.46,2806.73 U12.1@2312.18,2806
NetR184_1: R184.1 U12.10 | length 32.3
  Top Layer w7: U12.10@2422.42,2766.63 2451.07,2766.63 R184.1@2453.63,2764.07
NetR185_1: R185.1 U12.12 | length 34.9
  Top Layer w7: U12.12@2422.42,2806 2449.63,2806 2453.63,2810 R185.1@2453.63,2812.05
NetR186_1: R186.1 U12.3 | length 46.2
  Top Layer w8: R186.1@2277.36,2745.52 2277.36,2750.02 2280.86,2753.52 2289.24,2753.52 2297.39,2761.67 2300.14,2761.67 2305.1,2766.63 U12.3@2312.18,2766.63
NetR189_1: R189.1 U13.1 | length 81.8
  Top Layer w7: R189.1@2266.37,2468.39 2266.37,2465.77 2270.37,2461.77 2316.32,2461.77 U13.1@2335.79,2442.3
NetR190_1: R190.1 U13.10 | length 32
  Top Layer w7: U13.10@2446.03,2402.93 R190.1@2477.98,2402.93
NetR191_1: R191.1 U13.12 | length 32.5
  Top Layer w7: U13.12@2446.03,2442.3 2476.72,2442.3 R191.1@2477.98,2441.05
NetR192_1: R192.1 U13.3 | length 41.9
  Top Layer w7: R192.1@2302.79,2383.75 2302.79,2385.37 2306.79,2389.37 2309.84,2389.37 2322.19,2401.71 2334.57,2401.71 U13.3@2335.79,2402.93
PG1: R16.1 U1.B12 | length 407.4
  Top Layer w7: v2(2937.8,3182.59) 2938.07,3182.59 2951.09,3169.57 U1.B12@2951.09,3169.06
  Top Layer w10: R16.1@2674.09,3448.85 v2(2695.74,3448.85)
  Signal Layer 2 w10: v2(2695.74,3448.85) 2816.77,3327.82 2816.77,3303.62 v2(2937.8,3182.59)
PG2: R17.1 U1.B10 | length 562.2
  Top Layer w7: v2(2937.08,3121.46) 2937.08,3121.17 2951.37,3106.87 U1.B10@2951.37,3106.81
  Top Layer w10: v2(2565.04,3424) R17.1@2565.04,3448.85
  Signal Layer 2 w10: v2(2565.04,3424) 2565.04,3390.83 2759.2,3196.67 2837.05,3196.67 2912.25,3121.46 v2(2937.08,3121.46)
PG3: R20.1 U1.B5 | length 484.7
  Top Layer w7: v2@2935.79,2965.36 2935.91,2965.36 2951.3,2949.97 U1.B5@2951.42,2949.97
  Top Layer w10: R20.1@2586.16,2736.42 v2(2586.16,2763.18)
  Signal Layer 2 w10: v2(2586.16,2763.18) 2755.77,2932.78 2876.62,2932.78 2896.46,2952.62 2925.64,2952.62 2936.61,2963.6 v2(2936.61,2964.42)
  Bottom Layer w10: v2@2935.46,2963.28 v2(2936.61,2964.42)
PG4: R21.1 U1.B3 | length 342.3
  Top Layer w7: v2@2937.86,2900.52 U1.B3@2951.4,2886.98
  Top Layer w10: R21.1@2695.74,2736.42 v2(2714.7,2736.42)
  Signal Layer 2 w10: v2(2714.7,2736.42) 2793.59,2815.31 2793.59,2838.03 2837.46,2881.9 2919.24,2881.9 v2(2937.7,2900.36)
PGND: C6.2 C7.2 C8.2 C10.2 C13.2 C14.2 C15.2 C16.2 C18.2 C19.2 C20.2 C21.2 C22.2 C23.2 C24.2 C26.2 C27.2 C28.2 C29.2 C31.2 C32.2 C33.2 C34.2 C35.2 C36.2 C37.2 C38.2 C39.2 C40.2 C41.2 C42.2 C43.2 C44.2 C45.2 C46.2 C47.2 C48.2 C49.2 C50.2 C51.2 C52.2 C53.2 C54.2 C56.2 C57.2 C58.2 C59.2 C60.2 C61.2 C62.2 C63.2 C97.2 C99.2 C104.2 C105.2 C116.2 C117.2 C118.2 C119.2 C120.2 C121.2 C122.2 C123.2 C124.2 C125.2 J3.1 J8.4 J9.2 J10.1 J12.1 J14.4 J15.2 J16.1 J17.1 J20.2 J20.3 J22.1 NT1.1 pad.2@3063.58,3128.37 pad.2@3065.52,2919.41 R70.1 R71.1 R72.1 R73.1 R110.1 R112.2 R113.1 TP10.1 TP11.1 U1.C1 U1.C2 U1.C3 U1.C4 U1.C5 U1.C6 U1.C7 U1.C8 U1.C9 U1.C10 U1.C11 U1.C12 U1.C13 U1.C14 U1.D4 U1.D11 U1.E3 U1.E4 U1.E5 U1.E10 U1.E11 U1.E12 U1.F3 U1.F4 U1.F5 U1.F10 U1.F11 U1.F12 U1.G3 U1.G4 U1.G5 U1.G10 U1.G11 U1.G12 U1.H3 U1.H4 U1.H5 U1.H10 U1.H11 U1.H12 U8.2 | length 1490.6
  Top Layer w10: v2(183.41,4122.46) 183.41,4101.22 C99.2@184.06,4100.58 ; R112.2@228.34,3722.94 228.79,3723.39 v2(228.79,3751.23) ; v2(260.83,3794.65) 261.05,3794.88 261.05,3828.1 U8.2@261.28,3828.32 ; R110.1@365.09,3919.34 365.35,3919.08 365.35,3893.54 v2(365.61,3893.28) ; C118.2@4571.26,4288.1 v4(4596.66,4288.1) ; C116.2@4571.53,4243.15 v4(4596.66,4243.15) ; C121.2@5267.57,1673.48 v4(5267.57,1707.32) ; C117.2@5271.33,3830.83 v4(5271.33,3857.15) ; v4(5303.36,2649.38) C122.2@5303.36,2681.25 ; C123.2@5313.67,1671.7 v4(5313.67,1706.68) ; C119.2@5320,3831.11 v4(5320,3857.48) ; v4(5349.8,2649.45) C120.2@5349.8,2681.32
  Top Layer w15: C97.2@375.45,4070.58 377.85,4072.99 v2(377.85,4151.46) ; v1(3232.85,3221.61) 3233.64,3222.39 3233.64,3242.72 C26.2@3234.42,3242.72 ; v1(3233.86,2819.59) 3233.86,2771.59 C29.2@3234.21,2771.59 ; C28.2@3234.42,2928.8 3238.92,2928.8 3250.88,2916.84 3274.17,2916.84 C37.2@3291.67,2899.34 ; C27.2@3234.42,3134.15 3263.75,3134.15 3285.17,3155.58 C32.2@3291.67,3155.58
  Top Layer w20: R113.1@648.25,3660.61 648.25,3709.65 C104.2@633.01,3724.89 ; v2(838.77,3724.89) C104.2@633.01,3724.89 ; C104.2@633.01,3724.89 617.35,3724.89 C104.2@617,3725.24 632.66,3725.24 C104.2@633.01,3724.89
  Top Layer w30: J3.1@142.74,4304.95 237.79,4400 629.64,4400 J22.1@644.6,4414.96
  other v1: 4911.18,1591.41 5574.59,1681.53 5631.12,1684.84 4903.2,1731.12 4916.22,1827.27 5084.86,1827.27 5139.39,1827.27 5190,1827.27 4916.22,1881.81 4916.22,1932.42 4916.22,1975.93 4916.22,2022.41 4916.22,2068.04 4818.04,2110 4773.58,2142.05 5159.23,2160 5213.77,2160 5264.38,2160 5307.89,2160 5354.37,2160 5400,2160 4679.88,2227 4620.01,2302.83 4500.01,2429.5 4460.01,2462.26 4415,2510.47 4359.26,2567.25 4316.45,2608.11 4560,2610 5075.52,2610 5139.73,2610 2919.04,2645.27 2922.17,2672.37 5423,2680 5500,2680 4205.95,2692.09 2920.83,2700.07 4401.24,2726.07 4675.53,2726.07 2920.83,2727.26 4455.33,2727.7 4497.81,2728.45 4532.54,2728.45 2905.3,2751.97 2872.62,2761.65 3731.97,2785.77 3460.8,2790.68 3597.07,2790.92 4080.19,2807.81 3597.07,2817.98 4249.89,2817.98 3460.8,2819.59 4163.04,2839.07 3325.15,2860.37 3185.55,2867.19 3460.8,2890.44 3206.54,2915.19 3554.05,2914.98 3592.49,2914.98 3627.59,2914.98 3420.99,2916.15 3453.14,2916.15 3517.67,2915.62 3708.27,2916.15 3352.19,2918.47 3386.87,2917.64 3165.35,2921.79 3203.19,3129.43 3356.66,3133.92 3413.36,3133.59 3523.74,3135.79 3560.03,3135.79 3608.75,3135.79 3460.8,3136.8 3205.74,3190.1 3297.67,3195.67 3324.71,3196.95 3206.54,3220.11 3460.8,3221.61 3460.8,3249.85 4085.21,3249.85 4184.36,3256.05 2970.19,3257.35 3519.08,3275.38 3550.12,3275.38 3632.29,3275.38 3672.12,3275.38 3708.64,3275.38 4155.24,3292.6 2917.28,3293.7 4242.82,3308.34 2917.28,3321.3 4191.36,3335.13 4286.69,3349.19 2914.7,3353.09 2941.21,3361.43 2970.19,3361.43 4235.23,3375.97 4332.58,3394.57 4281.12,3421.36 3214.15,3447.78 4329.03,3468.26 4416.84,3475.18 3246.8,3480.34 3275.02,3505.69 4448.44,3512.13 3352.19,3531.91 3404.84,3531.91 4492.32,3552.98 4410.32,3571.66 4538.2,3598.37 1383.7,3620.87 1436,3620.51 1466.45,3621.6 1503.73,3621.9 4410.32,3626.19 1531.34,3639.83 1342.59,3649.11 4410.32,3675.04 1343.06,3677.02 1531.34,3678.44 4617.21,3680.6 1344.48,3707.3 1531.34,3715.99 4648.61,3716.21 1503.73,3736.46 1463.7,3737.55 1383.7,3738.64 1436,3738.64 4873.52,3796.16 4940.98,3796.82 5611.02,3857.15 4054.15,3886.3 4054.15,3940.83 4054.15,3991.44 4949.13,4012.74 5003.67,4012.74 5054.28,4012.74 5097.79,4012.74 5144.27,4012.74 5189.9,4012.74 4054.15,4034.95 4054.15,4081.43 4054.15,4127.06 4777.36,4243.15 4831.89,4243.15 4882.5,4243.15 4926.01,4243.15 4972.5,4243.15 5018.13,4243.15 5344.38,4310 5387.89,4310 5434.37,4310 5480,4310 4054.15,4365.33 5120,4370 5120,4415.63 4054.15,4419.86 5120,4462.11 4054.15,4470.47 5120,4505.62 4054.15,4513.98 5120,4556.23 4054.15,4560.46 4054.15,4606.09 5120,4610.77
  other v2: 1009.44,4055.82 1014.55,4137.68
  other v6: 2969.74,2839.86 2969.74,2871.3 2969.74,2902.43 3092.81,2901.9 3121.5,2901.55 2969.74,2933.84 3093.92,2933.62 3121.5,2935.82 2969.74,2966.15 2969.74,2996.98 2969.74,3028.71 2969.74,3060.82 2968.42,3092 2970.19,3121.31 3125.72,3122.05 3093.87,3124.01 3093.68,3153.63 3125.53,3153.63 2969.74,3155.16 2969.74,3186.52 2969.74,3217.85
REF4V1: C86.1 R74.2 U3.54 | length 1242.2
  Top Layer w8: U3.54@3313.22,2204.68 3392.18,2204.68 3401.54,2195.32 3447.43,2195.32 3461.2,2181.56 3468.7,2181.56 3474.7,2175.56 C86.1@3474.7,2168.06
  Top Layer w10: R74.2@3335.6,1238.46 3335.6,1242.96 3338.1,1245.46 3341.34,1245.46 3561.66,1465.79 3561.66,2032.89 3474.7,2119.86 C86.1@3474.7,2168.06
REF_0.4V: R187.2 R188.2 R189.2 R190.2 R191.2 R192.2 | length 596
  Top Layer w7: R187.2@2187.16,2469.47 2225.3,2469.47 R189.2@2226.37,2468.39 2223.16,2465.19 2223.16,2446.18 ; R188.2@2223.16,2438.62 2223.16,2446.18 ; R192.2@2262.79,2383.75 2262.79,2385.37 2258.79,2389.37 2254.65,2389.37 2244.66,2399.36 2244.66,2421.62 2229.19,2437.09 2229.19,2440.15 2223.16,2446.18
  Top Layer w10: R192.2@2262.79,2383.75 2262.79,2346.72 2327.74,2281.76 2459.19,2281.76 2517.98,2340.55 R190.2@2517.98,2402.93 R191.2@2517.98,2441.05
RELAY_IN1: Q6.7 Q6.8 Q6.9 R35.2 R41.2 | length 47.5
  Bottom Layer w15: R41.2@3948.02,3453.49 3948.02,3428.57 v2(3963.97,3412.62)
  other v1: 4158.47,3403.62 4190.07,3440.57 4067.17,3463.56 4233.94,3481.41 4065.71,3515.97 4279.83,3526.8 4067.17,3570.51 4326.43,3570.51 4080.19,3613.85 4326.43,3625.04 4030,3660 4326.43,3673.89 4210.52,3713.7 4109.76,3736.48
RELAY_IN2: Q5.7 Q5.8 Q5.9 R40.2 R53.2 | length 35.9
  Bottom Layer w15: v2(3952.82,3159.48) 3953.01,3159.67 3953.01,3194.72 R53.2@3953.45,3195.16
  other v1: 4350.19,3063.41 4404.72,3063.41 4455.33,3063.41 4498.84,3063.41 4545.33,3063.41 4339.45,3110 4660.71,3144.78 4150,3157.37 4191.98,3157.37 4242.59,3157.37 4286.1,3157.37 4332.58,3157.37 4254.97,3224.53 4299.96,3269.34 4673,3306.02 4673,3356.47 4409.08,3367.26 4452.95,3408.11 4673.85,3420.19 4498.84,3453.49 4555.43,3459.66 4675.31,3474.73 4555.43,3510.45 4643.01,3598.37 4675.63,3621.62
RELAY_IN3: Q11.7 Q11.8 Q11.9 R55.2 R57.2 | length 45.4
  Bottom Layer w15: v2(3954.28,2899.34) 3954.47,2899.15 3954.47,2856.52 R57.2@3956.27,2854.72
  other v1: 4704.29,2826.76 4656.04,2830.62 4329.48,2837.62 4460.01,2844.07 4530.5,2843.64 4704.29,2873.25 4269.38,2884.7 4764.09,2931.18 4560,2960.4 4646.1,2974.69 4345.55,2988.14 4513.04,2989.41 4410.43,2991.28 4464.58,2990.5 4684.46,2993.63 4184.24,2996.97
